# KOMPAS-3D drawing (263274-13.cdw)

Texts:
  Крышка
  Loner-XP
  WolfishLair
  Текст на чертеже
  Размерные надписи
  Шероховатость
  Линия-выноска #1
  Линия-выноска #2
  Линия-выноска #3
  Отклонения формы и база
  Заголовок таблицы
  Ячейка таблицы
  Стрелка вида
  Обозначение изменения
  Фигурная скобка
  Номер узла
  Марка координационной оси
  VRCB
  Выносная надпись
  Обозначение узла
  Марка/позиционное обозначение с линией-выноской
  Марка/позиционное обозначение на линии
  Марка/позиционное обозначение без линии-выноски
  Rz 40
  Rz 20
  Месечко А.В.
  Овчаренко В.В.
  ВНУ им. Даля
  гр.МЗ - 06в
Dimensions and other numbers on the sheet: 701.048.00.004; 7; 46; 17,5; 10,5; 2.5; 134; 100; 88; 70; 5; 15; 114; 4 отв.; 6; 1:1; 1; 701.048.00.004-; 0; 2; 3; 4; 8; 9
